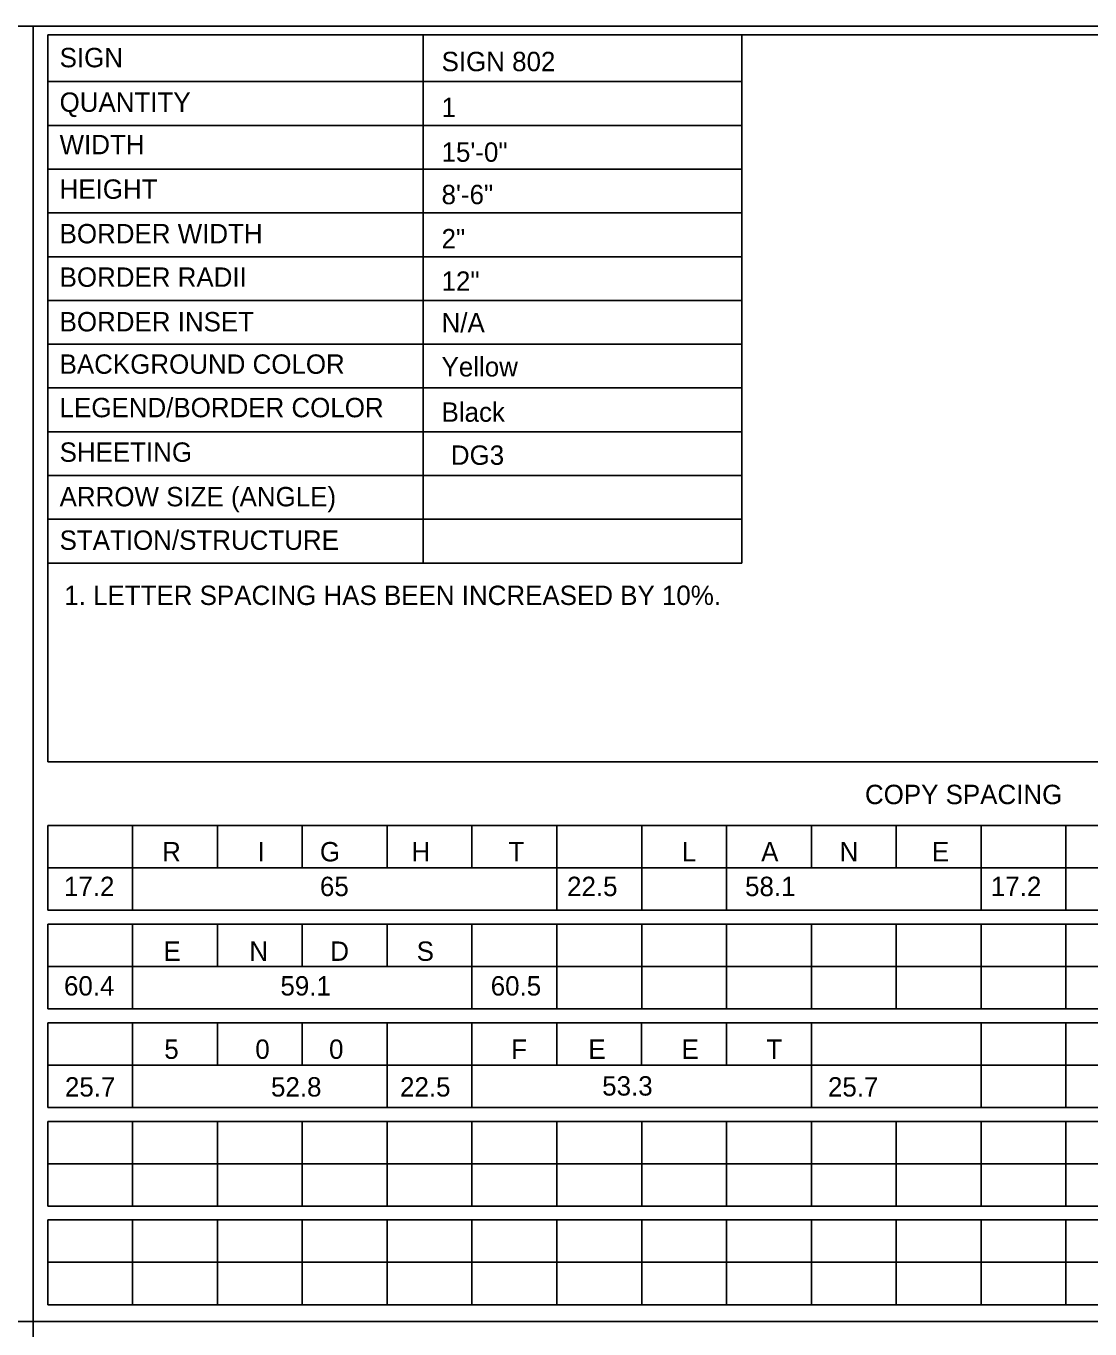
# Model space of a CAD drawing. Extents: x 10268147 to 10268469, y 2141099 to 2141204.
# Drawn here: x 10268229.47 to 10268267.89, y 2141156.92 to 2141203.96 of the extents above; entities that cross this region are included whole.
import ezdxf

# ---------------------------------------------------------------- set-up
doc = ezdxf.new("R2010")
doc.units = 0
for name, color, linetype in [('61', 7, 'Continuous'), ('North Arrow', 7, 'Continuous'), ('SheetLinesMisc2_dp', 7, 'Continuous'), ('TextMisc', 7, 'Continuous')]:
    doc.layers.add(name, color=color, linetype=linetype)

msp = doc.modelspace()

# ---------------------------------------------------------------- linework, layer by layer
at = {"layer": '61'}
for p, q in [((10268230.252, 2141203.638), (10268305.587, 2141203.638)), ((10268230.252, 2141177.389), (10268230.252, 2141203.638)), ((10268243.812, 2141203.638), (10268243.812, 2141184.572)), ((10268255.325, 2141203.638), (10268255.325, 2141184.572)), ((10268230.252, 2141201.949), (10268255.325, 2141201.949)), ((10268230.252, 2141200.37), (10268255.325, 2141200.37)), ((10268230.252, 2141198.79), (10268255.325, 2141198.79)), ((10268230.252, 2141197.21), (10268255.325, 2141197.21)), ((10268230.252, 2141195.63), (10268255.325, 2141195.63)), ((10268230.252, 2141194.051), (10268255.325, 2141194.051)), ((10268230.252, 2141192.471), (10268255.325, 2141192.471)), ((10268230.252, 2141190.891), (10268255.325, 2141190.891)), ((10268230.252, 2141189.311), (10268255.325, 2141189.311)), ((10268230.252, 2141187.731), (10268255.325, 2141187.731)), ((10268230.252, 2141186.152), (10268255.325, 2141186.152)), ((10268230.252, 2141184.572), (10268255.325, 2141184.572)), ((10268230.252, 2141177.389), (10268305.587, 2141177.389)), ((10268230.252, 2141175.094), (10268305.587, 2141175.094)), ((10268230.252, 2141175.094), (10268230.252, 2141172.034)), ((10268230.252, 2141175.094), (10268230.252, 2141172.034)), ((10268233.318, 2141175.094), (10268233.318, 2141172.034)), ((10268233.318, 2141175.094), (10268233.318, 2141172.034)), ((10268236.382, 2141175.094), (10268236.382, 2141173.564)), ((10268236.382, 2141175.094), (10268236.382, 2141173.564)), ((10268239.446, 2141175.094), (10268239.446, 2141173.564)), ((10268239.446, 2141175.094), (10268239.446, 2141173.564)), ((10268242.511, 2141175.094), (10268242.511, 2141173.564)), ((10268242.511, 2141175.094), (10268242.511, 2141173.564)), ((10268245.575, 2141175.094), (10268245.575, 2141173.564)), ((10268245.575, 2141175.094), (10268245.575, 2141173.564)), ((10268248.64, 2141175.094), (10268248.64, 2141172.034)), ((10268248.64, 2141175.094), (10268248.64, 2141172.034)), ((10268251.705, 2141175.094), (10268251.705, 2141172.034)), ((10268251.705, 2141175.094), (10268251.705, 2141172.034)), ((10268254.769, 2141175.094), (10268254.769, 2141172.034)), ((10268254.769, 2141175.094), (10268254.769, 2141173.564)), ((10268257.833, 2141175.094), (10268257.833, 2141173.564)), ((10268257.833, 2141175.094), (10268257.833, 2141173.564)), ((10268260.898, 2141175.094), (10268260.898, 2141173.564)), ((10268260.898, 2141175.094), (10268260.898, 2141173.564)), ((10268263.963, 2141175.094), (10268263.963, 2141172.034)), ((10268263.963, 2141175.094), (10268263.963, 2141172.034)), ((10268267.027, 2141175.094), (10268267.027, 2141172.034)), ((10268267.027, 2141175.094), (10268267.027, 2141172.034)), ((10268230.252, 2141173.564), (10268294.609, 2141173.564)), ((10268230.252, 2141173.564), (10268294.609, 2141173.564)), ((10268230.252, 2141172.034), (10268305.587, 2141172.034)), ((10268230.252, 2141171.535), (10268305.587, 2141171.535)), ((10268230.252, 2141171.535), (10268230.252, 2141168.475)), ((10268230.252, 2141171.535), (10268230.252, 2141168.475)), ((10268233.318, 2141171.535), (10268233.318, 2141168.475)), ((10268233.318, 2141171.535), (10268233.318, 2141168.475)), ((10268236.382, 2141171.535), (10268236.382, 2141170.005)), ((10268236.382, 2141171.535), (10268236.382, 2141170.005)), ((10268239.446, 2141171.535), (10268239.446, 2141170.005)), ((10268239.446, 2141171.535), (10268239.446, 2141170.005)), ((10268242.511, 2141171.535), (10268242.511, 2141170.005)), ((10268242.511, 2141171.535), (10268242.511, 2141170.005)), ((10268245.575, 2141171.535), (10268245.575, 2141168.475)), ((10268245.575, 2141171.535), (10268245.575, 2141168.475)), ((10268248.64, 2141171.535), (10268248.64, 2141168.475)), ((10268248.64, 2141171.535), (10268248.64, 2141168.475)), ((10268251.705, 2141171.535), (10268251.705, 2141168.475)), ((10268251.705, 2141171.535), (10268251.705, 2141168.475)), ((10268254.769, 2141171.535), (10268254.769, 2141168.475)), ((10268254.769, 2141171.535), (10268254.769, 2141168.475)), ((10268257.833, 2141171.535), (10268257.833, 2141168.475)), ((10268257.833, 2141171.535), (10268257.833, 2141168.475)), ((10268260.898, 2141171.535), (10268260.898, 2141168.475)), ((10268260.898, 2141171.535), (10268260.898, 2141168.475)), ((10268263.963, 2141171.535), (10268263.963, 2141168.475)), ((10268263.963, 2141171.535), (10268263.963, 2141168.475)), ((10268267.027, 2141171.535), (10268267.027, 2141168.475)), ((10268267.027, 2141171.535), (10268267.027, 2141168.475)), ((10268230.252, 2141170.005), (10268294.609, 2141170.005)), ((10268230.252, 2141170.005), (10268294.609, 2141170.005)), ((10268230.252, 2141168.475), (10268305.587, 2141168.475)), ((10268230.252, 2141167.976), (10268305.587, 2141167.976)), ((10268230.252, 2141167.976), (10268230.252, 2141164.915)), ((10268230.252, 2141167.976), (10268230.252, 2141164.915)), ((10268233.318, 2141167.976), (10268233.318, 2141164.915)), ((10268233.318, 2141167.976), (10268233.318, 2141164.915)), ((10268236.382, 2141167.976), (10268236.382, 2141166.445)), ((10268236.382, 2141167.976), (10268236.382, 2141166.445)), ((10268239.446, 2141167.976), (10268239.446, 2141166.445)), ((10268239.446, 2141167.976), (10268239.446, 2141166.445)), ((10268242.511, 2141167.976), (10268242.511, 2141164.915)), ((10268242.511, 2141167.976), (10268242.511, 2141166.445)), ((10268242.511, 2141167.976), (10268242.511, 2141164.915)), ((10268242.511, 2141167.976), (10268242.511, 2141164.915)), ((10268245.576, 2141167.976), (10268245.576, 2141164.915)), ((10268245.576, 2141167.976), (10268245.576, 2141164.915)), ((10268248.64, 2141167.976), (10268248.64, 2141166.445)), ((10268248.64, 2141167.976), (10268248.64, 2141166.445)), ((10268251.704, 2141167.976), (10268251.704, 2141166.445)), ((10268251.704, 2141167.976), (10268251.704, 2141166.445)), ((10268254.769, 2141167.976), (10268254.769, 2141166.445)), ((10268254.769, 2141167.976), (10268254.769, 2141166.445)), ((10268257.834, 2141167.976), (10268257.834, 2141164.915)), ((10268257.834, 2141167.976), (10268257.834, 2141164.915)), ((10268263.963, 2141167.976), (10268263.963, 2141164.915)), ((10268263.963, 2141167.976), (10268263.963, 2141164.915)), ((10268267.027, 2141167.976), (10268267.027, 2141164.915)), ((10268267.027, 2141167.976), (10268267.027, 2141164.915)), ((10268230.252, 2141166.445), (10268294.609, 2141166.445)), ((10268230.252, 2141166.445), (10268294.609, 2141166.445)), ((10268230.252, 2141164.915), (10268305.587, 2141164.915)), ((10268230.252, 2141164.416), (10268305.587, 2141164.416)), ((10268230.252, 2141164.416), (10268230.252, 2141161.355)), ((10268233.318, 2141164.416), (10268233.318, 2141161.355)), ((10268236.382, 2141164.416), (10268236.382, 2141161.355)), ((10268239.446, 2141164.416), (10268239.446, 2141161.355)), ((10268242.511, 2141164.416), (10268242.511, 2141161.355)), ((10268245.575, 2141164.416), (10268245.575, 2141161.355)), ((10268248.64, 2141164.416), (10268248.64, 2141161.355)), ((10268251.705, 2141164.416), (10268251.705, 2141161.355)), ((10268254.769, 2141164.416), (10268254.769, 2141161.355)), ((10268257.833, 2141164.416), (10268257.833, 2141161.355)), ((10268260.898, 2141164.416), (10268260.898, 2141161.355)), ((10268263.963, 2141164.416), (10268263.963, 2141161.355)), ((10268267.027, 2141164.416), (10268267.027, 2141161.355)), ((10268230.252, 2141162.886), (10268294.609, 2141162.886)), ((10268230.252, 2141161.355), (10268305.587, 2141161.355)), ((10268230.252, 2141160.856), (10268305.587, 2141160.856)), ((10268230.252, 2141160.856), (10268230.252, 2141157.796)), ((10268233.318, 2141160.856), (10268233.318, 2141157.796)), ((10268236.382, 2141160.856), (10268236.382, 2141157.796)), ((10268239.446, 2141160.856), (10268239.446, 2141157.796)), ((10268242.511, 2141160.856), (10268242.511, 2141157.796)), ((10268245.575, 2141160.856), (10268245.575, 2141157.796)), ((10268248.64, 2141160.856), (10268248.64, 2141157.796)), ((10268251.705, 2141160.856), (10268251.705, 2141157.796)), ((10268254.769, 2141160.856), (10268254.769, 2141157.796)), ((10268257.833, 2141160.856), (10268257.833, 2141157.796)), ((10268260.898, 2141160.856), (10268260.898, 2141157.796)), ((10268263.963, 2141160.856), (10268263.963, 2141157.796)), ((10268267.027, 2141160.856), (10268267.027, 2141157.796)), ((10268230.252, 2141159.327), (10268294.609, 2141159.327)), ((10268230.252, 2141157.796), (10268305.587, 2141157.796))]:
    msp.add_line(p, q, dxfattribs=at)
at = {"layer": 'SheetLinesMisc2_dp'}
for p, q in [((10268153.14, 2141203.955), (10268306.32, 2141203.955)), ((10268229.73, 2141203.955), (10268229.73, 2141110.434)), ((10268153.14, 2141157.195), (10268306.32, 2141157.195))]:
    msp.add_line(p, q, dxfattribs=at)

# ---------------------------------------------------------------- texts
at = {"layer": 'North Arrow'}
for s, p in [('SIGN 802', (10268244.477, 2141202.326)), ('1', (10268244.477, 2141200.671)), ('15\'-0"', (10268244.477, 2141199.056)), ('8\'-6"', (10268244.477, 2141197.524)), ('2"', (10268244.477, 2141195.93)), ('12"', (10268244.477, 2141194.398)), ('N/A', (10268244.477, 2141192.899)), ('Yellow', (10268244.477, 2141191.305)), ('Black', (10268244.477, 2141189.67)), ('R', (10268234.384, 2141173.8)), ('I', (10268237.834, 2141173.8)), ('G', (10268240.084, 2141173.8)), ('H', (10268243.388, 2141173.8)), ('T', (10268246.894, 2141173.8)), ('L', (10268253.152, 2141173.8)), ('A', (10268256.02, 2141173.8)), ('N', (10268258.852, 2141173.8)), ('E', (10268262.187, 2141173.8)), ('17.2', (10268230.84, 2141172.547)), ('65', (10268240.084, 2141172.547)), ('22.5', (10268249.01, 2141172.547)), ('58.1', (10268255.439, 2141172.547)), ('17.2', (10268264.315, 2141172.547)), ('E', (10268234.43, 2141170.21)), ('N', (10268237.535, 2141170.21)), ('D', (10268240.458, 2141170.21)), ('S', (10268243.578, 2141170.21)), ('60.4', (10268230.84, 2141168.958)), ('59.1', (10268238.658, 2141168.958)), ('60.5', (10268246.252, 2141168.958)), ('5', (10268234.463, 2141166.671)), ('0', (10268237.749, 2141166.671)), ('0', (10268240.414, 2141166.671)), ('F', (10268246.992, 2141166.671)), ('E', (10268249.778, 2141166.671)), ('E', (10268253.146, 2141166.671)), ('T', (10268256.208, 2141166.671)), ('25.7', (10268230.875, 2141165.311)), ('52.8', (10268238.317, 2141165.311)), ('22.5', (10268242.977, 2141165.311)), ('53.3', (10268250.279, 2141165.346)), ('25.7', (10268258.433, 2141165.311))]:
    msp.add_text(s, height=0.7, dxfattribs=at).set_placement(p)
at = {"layer": 'TextMisc'}
for s, p in [('SIGN', (10268230.682, 2141202.467)), ('QUANTITY', (10268230.682, 2141200.858)), ('WIDTH', (10268230.682, 2141199.327)), ('HEIGHT', (10268230.682, 2141197.719)), ('BORDER WIDTH', (10268230.682, 2141196.111)), ('BORDER RADII', (10268230.682, 2141194.542)), ('BORDER INSET', (10268230.682, 2141192.933)), ('BACKGROUND COLOR', (10268230.682, 2141191.402)), ('LEGEND/BORDER COLOR', (10268230.682, 2141189.833)), ('SHEETING', (10268230.682, 2141188.225)), ('DG3', (10268244.813, 2141188.116)), ('ARROW SIZE (ANGLE)', (10268230.682, 2141186.617)), ('STATION/STRUCTURE', (10268230.682, 2141185.047)), ('1. LETTER SPACING HAS BEEN INCREASED BY 10%.', (10268230.85, 2141183.056)), ('COPY SPACING', (10268259.769, 2141175.867))]:
    msp.add_text(s, height=0.7, dxfattribs=at).set_placement(p)

doc.saveas('drawing.dxf')
